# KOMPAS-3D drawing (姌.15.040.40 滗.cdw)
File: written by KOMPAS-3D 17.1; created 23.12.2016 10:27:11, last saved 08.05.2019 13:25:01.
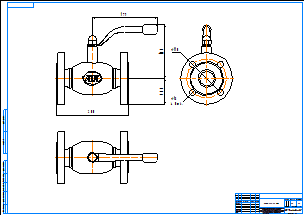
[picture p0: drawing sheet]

Sheet 1: A1, landscape

Title block, sheet 1: name: КШ.15.040.40 фф; material: Внимание! Данный продукт является объектом авторского права ООО «Торговый Дом АДЛ». / Запрещается изменение, копирование, распространение / (в том числе путем копирования на другие сайты и ресурсы в Интернете) / или любое иное использование информации и объектов без предварительного / согласия правообладателя (ООО «Торговый Дом АДЛ»).; mass: 1,3; sheets: 1; organisation: ООО "Торговый дом АДЛ"; sheet format: A1; stored path: C:\Users\tra\Desktop\2д чертежи\Шаровые краны БИВАЛ\КШ_Бивал_серия_14_15\KOMPAS_2D\КШ.15.040.40 фф.cdw

Views: Вид 1, Проекционный вид 2, Проекционный вид 3
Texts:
  Klimkovich
  ADL
Dimensions and other numbers on the sheet: 200; 179; 148; 72,5; 110; 18; 4 Отв.; 1:1; 1; 1,3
